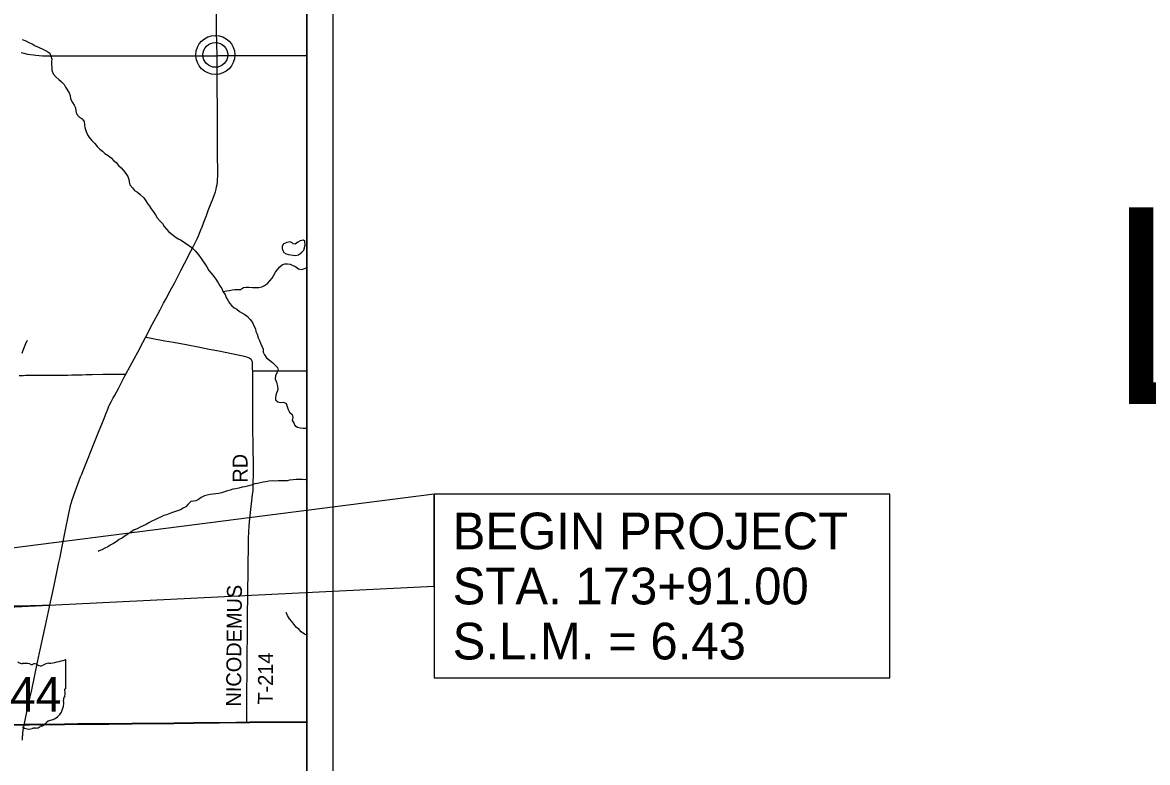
# Model space of a CAD drawing. Extents: x 0 to 34, y 0 to 22.
# Drawn here: x 7.83 to 12.121, y 17.09 to 19.912 of the extents above; entities that cross this region are included whole.
import ezdxf

# ---------------------------------------------------------------- set-up
doc = ezdxf.new("R2010")
doc.units = 0
for name, color, linetype in [('GM_X_Corporation', 7, 'Continuous'), ('GM_X_County_Road', 7, 'Continuous'), ('GM_X_Minor_Lake', 7, 'Continuous'), ('GM_X_Minor_River', 7, 'Continuous'), ('GM_X_State_Location', 7, 'Continuous'), ('GM_X_State_Route', 7, 'Continuous'), ('GM_X_State_Shield', 7, 'Continuous'), ('GM_X_Township_Road', 7, 'Continuous'), ('GM_X_Township_Road_Text', 7, 'Continuous'), ('GM_X_Unincorporated', 7, 'Continuous'), ('GM_X_Unincorporated_Location', 7, 'Continuous'), ('SH_Data', 7, 'Continuous'), ('SH_Text', 7, 'Continuous')]:
    doc.layers.add(name, color=color, linetype=linetype)

msp = doc.modelspace()

# ---------------------------------------------------------------- linework, layer by layer
at = {"layer": 'GM_X_Corporation'}
for points in [[(7.6782, 17.2342), (7.8362, 17.2347), (7.8566, 17.2348), (7.9908, 17.2361), (8.015, 17.2365), (8.0417, 17.237), (8.1363, 17.2369), (8.1597, 17.237), (8.2138, 17.2377), (8.2474, 17.2382), (8.3164, 17.2393), (8.4071, 17.2399), (8.4823, 17.2409), (8.5289, 17.2412), (8.5818, 17.2419), (8.6445, 17.2426), (8.6851, 17.2432), (8.6974, 17.2434), (8.762, 17.244), (8.8285, 17.2444), (8.8621, 17.2445), (8.914, 17.2449), (8.914, 20.6173), (5.0338, 20.6173)], [(5.0539, 13.8173), (8.914, 13.8173), (8.914, 17.2449), (8.8621, 17.2445), (8.8285, 17.2444), (8.762, 17.244), (8.6974, 17.2434), (8.6851, 17.2432), (8.6445, 17.2426), (8.5818, 17.2419), (8.5289, 17.2412), (8.4823, 17.2409), (8.4071, 17.2399), (8.3164, 17.2393), (8.2474, 17.2382), (8.2138, 17.2377), (8.1597, 17.237), (8.1363, 17.2369), (8.0417, 17.237), (8.015, 17.2365), (7.9908, 17.2361), (7.8566, 17.2348), (7.8362, 17.2347), (7.6782, 17.2342)]]:
    msp.add_lwpolyline(points, dxfattribs=at)
at = {"layer": 'GM_X_County_Road'}
for points in [[(7.8175, 18.5661), (7.8342, 18.5665), (7.8416, 18.5667), (7.8531, 18.5668), (7.8629, 18.5668), (7.8685, 18.5668), (7.8809, 18.5667), (7.902, 18.567), (7.9137, 18.5671), (7.9404, 18.567), (7.9683, 18.5672), (7.9881, 18.5675), (8.0037, 18.5678), (8.018, 18.5681), (8.0347, 18.5685), (8.0446, 18.5687), (8.0582, 18.569), (8.073, 18.5692), (8.0956, 18.5696), (8.1365, 18.5705), (8.1651, 18.5714), (8.1883, 18.5713), (8.2082, 18.5713), (8.2176, 18.5709), (8.2245, 18.5706)], [(7.0381, 17.229), (7.0647, 17.2291), (7.09, 17.2291), (7.1124, 17.2293), (7.1384, 17.2293), (7.1595, 17.2294), (7.305, 17.2305), (7.3566, 17.2307), (7.382, 17.2308), (7.5492, 17.2324), (7.62, 17.2331), (7.6784, 17.2336), (7.8364, 17.2342)], [(7.8364, 17.2342), (7.8568, 17.2342), (7.991, 17.2356), (8.0152, 17.2359), (8.0419, 17.2364), (8.1365, 17.2363), (8.1599, 17.2365), (8.214, 17.2371), (8.2476, 17.2376), (8.3166, 17.2387), (8.4073, 17.2394), (8.4825, 17.2403), (8.5291, 17.2407), (8.582, 17.2414), (8.6447, 17.242), (8.6853, 17.2427)], [(8.6853, 17.2427), (8.6976, 17.2429), (8.7622, 17.2435), (8.8287, 17.2439), (8.8623, 17.244), (8.914, 17.2444)]]:
    msp.add_lwpolyline(points, dxfattribs=at)
at = {"layer": 'GM_X_Minor_Lake'}
msp.add_line((8.8453, 19.0275), (8.8716, 19.0238), dxfattribs=at)
msp.add_lwpolyline([(8.8716, 19.0238), (8.8828, 19.0257), (8.8952, 19.0357), (8.9027, 19.0445), (8.9078, 19.0624), (8.9076, 19.0776), (8.9023, 19.0821), (8.8898, 19.0801), (8.88, 19.0747), (8.8699, 19.0673), (8.8627, 19.0684), (8.8588, 19.0721), (8.8505, 19.0755), (8.8384, 19.0734), (8.8244, 19.0664), (8.8203, 19.058), (8.8204, 19.0504), (8.8228, 19.0425), (8.8267, 19.0345), (8.8358, 19.0297), (8.8453, 19.0275)], dxfattribs=at)
at = {"layer": 'GM_X_Minor_River'}
for points in [[(7.8287, 19.8478), (7.8424, 19.8418), (7.8546, 19.8355), (7.8668, 19.8307), (7.8779, 19.8236), (7.8889, 19.8188), (7.9125, 19.8085), (7.9232, 19.8025), (7.9342, 19.7951), (7.9385, 19.7837), (7.9417, 19.7739), (7.941, 19.7629), (7.9408, 19.7534), (7.9417, 19.7397), (7.9425, 19.7302), (7.9476, 19.7166), (7.9572, 19.7049), (7.9691, 19.6948), (7.9786, 19.6858), (7.9893, 19.6753), (7.9948, 19.6655), (8.0079, 19.6444), (8.0114, 19.6334), (8.0134, 19.6205), (8.0208, 19.6069), (8.0273, 19.5971), (8.0327, 19.5866), (8.034, 19.5752), (8.036, 19.5642), (8.0464, 19.5522), (8.0582, 19.5443), (8.0659, 19.5346), (8.0664, 19.5216), (8.0681, 19.5114), (8.0728, 19.4963), (8.0786, 19.4842), (8.0859, 19.4725), (8.0947, 19.4627), (8.1055, 19.4503), (8.1151, 19.439), (8.1246, 19.4297), (8.135, 19.4211), (8.1445, 19.4128), (8.1563, 19.4046), (8.1678, 19.3956), (8.1774, 19.3858), (8.1869, 19.3776), (8.1962, 19.3667), (8.2061, 19.3573), (8.2157, 19.3476), (8.2245, 19.3359), (8.2322, 19.3246), (8.2361, 19.314), (8.237, 19.3045), (8.2401, 19.2935), (8.2494, 19.2819), (8.2578, 19.2713), (8.2689, 19.2646), (8.2796, 19.2568), (8.2926, 19.2429), (8.3003, 19.232), (8.3065, 19.2222), (8.3142, 19.2112), (8.3215, 19.2014), (8.3284, 19.1917), (8.3369, 19.1785), (8.3442, 19.1675), (8.3545, 19.1559), (8.3638, 19.1453), (8.3703, 19.134), (8.3799, 19.1239), (8.388, 19.1141), (8.3998, 19.1051), (8.4109, 19.0958), (8.4235, 19.0872), (8.433, 19.0835)], [(8.433, 19.0835), (8.4471, 19.0742), (8.4567, 19.0671), (8.4673, 19.06), (8.4788, 19.0514), (8.4891, 19.0416), (8.5033, 19.0243), (8.5118, 19.0126), (8.5191, 19.0013), (8.5257, 18.9915), (8.5334, 18.9799), (8.5407, 18.9666), (8.5499, 18.9557), (8.5599, 18.9437), (8.5676, 18.9335), (8.5765, 18.9192), (8.5823, 18.9075), (8.5903, 18.8973), (8.5946, 18.8864), (8.6027, 18.8743), (8.6074, 18.8634), (8.6139, 18.8532), (8.6194, 18.8422), (8.6282, 18.8321), (8.6377, 18.8238), (8.6473, 18.819), (8.6572, 18.8104), (8.6671, 18.8052), (8.6786, 18.7981), (8.6881, 18.791), (8.6988, 18.7801), (8.7073, 18.7685), (8.7131, 18.7556), (8.7185, 18.7443), (8.7198, 18.7333), (8.7248, 18.7231), (8.7288, 18.7098), (8.7342, 18.6997), (8.7385, 18.6891), (8.7431, 18.6781), (8.7482, 18.6664), (8.7487, 18.6554), (8.7526, 18.6444), (8.7603, 18.6335), (8.7725, 18.6238), (8.7832, 18.6152), (8.7932, 18.6062), (8.8028, 18.5964), (8.8048, 18.5858), (8.8003, 18.5762), (8.7955, 18.5644), (8.7934, 18.5534), (8.7985, 18.5401), (8.802, 18.5303), (8.804, 18.5167), (8.8022, 18.5072), (8.7974, 18.4957), (8.7949, 18.4839), (8.795, 18.4733), (8.8046, 18.4658), (8.8141, 18.4632), (8.8251, 18.4637), (8.8357, 18.4597), (8.84, 18.4476), (8.8428, 18.4362), (8.8482, 18.4264), (8.8581, 18.4178), (8.8613, 18.4053), (8.8584, 18.3946), (8.8653, 18.3848), (8.8692, 18.375), (8.8788, 18.3691), (8.8909, 18.3669), (8.9008, 18.3651), (8.9114, 18.3645), (8.914, 18.3646)], [(8.5946, 18.8864), (8.6098, 18.8888), (8.6196, 18.8897), (8.6298, 18.8921), (8.6396, 18.8941), (8.6506, 18.8939), (8.662, 18.894), (8.6736, 18.901), (8.6835, 18.9026), (8.6933, 18.9023), (8.7073, 18.9018), (8.7191, 18.9011), (8.7312, 18.9013), (8.7429, 18.9044), (8.7527, 18.9087), (8.7644, 18.9165), (8.773, 18.9264), (8.7823, 18.9376), (8.789, 18.949), (8.7953, 18.9605), (8.8039, 18.9712), (8.811, 18.9808), (8.8215, 18.9897), (8.8313, 18.9921), (8.8408, 18.9914), (8.851, 18.9904), (8.8613, 18.9856), (8.8708, 18.9815), (8.883, 18.9722), (8.8925, 18.9704), (8.9031, 18.9728), (8.914, 18.9782)], [(7.8284, 18.6507), (7.8332, 18.6629), (7.8384, 18.6748), (7.8428, 18.6885), (7.8479, 18.6996), (7.8487, 18.7)], [(8.914, 18.169), (8.9102, 18.1682), (8.8984, 18.1692), (8.887, 18.1698), (8.8742, 18.1693), (8.8621, 18.168), (8.8488, 18.1671), (8.839, 18.1647), (8.8261, 18.1641), (8.8049, 18.1639), (8.7936, 18.1634), (8.7818, 18.164), (8.7697, 18.1627), (8.7587, 18.1607), (8.7478, 18.1594), (8.7372, 18.157), (8.7262, 18.1546), (8.716, 18.1522), (8.7025, 18.1479), (8.6885, 18.1443), (8.6787, 18.1415), (8.6681, 18.1399), (8.6549, 18.1367), (8.6443, 18.1343), (8.6329, 18.1319), (8.6228, 18.1287), (8.6118, 18.1259), (8.6009, 18.122), (8.5895, 18.1185), (8.5793, 18.1164), (8.5676, 18.1152), (8.5578, 18.1135), (8.5461, 18.1115), (8.5347, 18.1098), (8.5238, 18.1071), (8.5121, 18.1009)], [(8.5121, 18.1009), (8.502, 18.0924), (8.4918, 18.0885), (8.4819, 18.0872), (8.4717, 18.0848), (8.4624, 18.0752), (8.453, 18.0648), (8.4429, 18.0594), (8.4323, 18.0532), (8.418, 18.0489), (8.4055, 18.0449), (8.3923, 18.0402), (8.3799, 18.0351), (8.3689, 18.0316), (8.3561, 18.0257), (8.3448, 18.0203), (8.335, 18.0152), (8.3237, 18.0109), (8.3124, 18.0036), (8.3023, 17.9974), (8.2925, 17.9942), (8.2793, 17.9876), (8.2672, 17.9818), (8.2563, 17.9775), (8.2439, 17.9686), (8.2319, 17.9609), (8.2221, 17.9547), (8.2112, 17.947), (8.1995, 17.9404), (8.1879, 17.9319), (8.1773, 17.9253), (8.1672, 17.9202), (8.1555, 17.9121), (8.1442, 17.9078), (8.1333, 17.9012), (8.1227, 17.8977), (8.1186, 17.8946)], [(8.914, 17.5751), (8.9057, 17.5795), (8.8924, 17.5889), (8.8847, 17.5986), (8.8748, 17.6054), (8.8644, 17.6178), (8.8575, 17.6276), (8.8486, 17.6385), (8.8409, 17.6502), (8.8359, 17.6619), (8.8363, 17.6611)]]:
    msp.add_lwpolyline(points, dxfattribs=at)
at = {"layer": 'GM_X_State_Route'}
for points in [[(8.572, 19.7856), (8.5704, 19.8786), (8.5698, 19.9413), (8.5693, 20.0004), (8.5683, 20.1116), (8.5679, 20.1484), (8.5676, 20.1747)], [(7.8245, 19.7977), (7.8359, 19.7947), (7.8498, 19.7915), (7.8607, 19.7897), (7.8718, 19.7882), (7.8817, 19.7873), (7.8934, 19.7864), (7.9065, 19.7856), (7.9436, 19.7846), (8.028, 19.7844), (8.1281, 19.7847), (8.2118, 19.7849)], [(8.2118, 19.7849), (8.2646, 19.7851), (8.3174, 19.7851), (8.3776, 19.7848), (8.5198, 19.7849), (8.572, 19.7856)], [(8.5133, 19.1277), (8.5137, 19.1286), (8.5223, 19.1512), (8.5314, 19.1757), (8.5389, 19.1954), (8.5486, 19.221), (8.5568, 19.2424), (8.562, 19.2558), (8.5658, 19.2669), (8.5688, 19.277), (8.5707, 19.2848), (8.5724, 19.2945), (8.5735, 19.3031), (8.5743, 19.313), (8.5747, 19.3266), (8.5743, 19.4244), (8.5742, 19.5077), (8.5734, 19.6027), (8.5732, 19.6449), (8.5729, 19.6912), (8.5729, 19.7215), (8.572, 19.7856)], [(8.572, 19.7856), (8.5777, 19.7857), (8.6355, 19.7859), (8.6858, 19.7859), (8.7386, 19.786), (8.7852, 19.786), (8.8417, 19.7861), (8.8809, 19.7861), (8.914, 19.7862)], [(8.4482, 18.9932), (8.4734, 19.042), (8.4824, 19.0597), (8.486, 19.0666), (8.4961, 19.0875), (8.5013, 19.0988), (8.5082, 19.1148), (8.5133, 19.1277)], [(7.8364, 17.2342), (7.8373, 17.2385), (7.8412, 17.258), (7.8537, 17.3143), (7.8652, 17.3672), (7.8876, 17.473), (7.8954, 17.5082), (7.9177, 17.6127), (7.9328, 17.6833), (7.9345, 17.6906), (7.9394, 17.7124), (7.9509, 17.7652), (7.9693, 17.8522), (7.9735, 17.8729), (7.9804, 17.907), (7.9946, 17.9777), (8.0057, 18.0337), (8.0151, 18.0757), (8.0155, 18.0772), (8.0196, 18.0915), (8.0218, 18.0986), (8.0256, 18.1092), (8.052, 18.1796), (8.0559, 18.1894), (8.0626, 18.2061), (8.1072, 18.3182), (8.1226, 18.3561), (8.1385, 18.3953), (8.1489, 18.4219), (8.1552, 18.4374), (8.16, 18.4488), (8.1623, 18.4539), (8.1682, 18.4655), (8.1721, 18.4726), (8.1764, 18.4802), (8.1805, 18.4879), (8.196, 18.5169), (8.2185, 18.5591), (8.2245, 18.5706), (8.2411, 18.602), (8.2557, 18.6294), (8.2695, 18.6551), (8.2886, 18.6914), (8.2991, 18.7111), (8.3038, 18.7199), (8.3188, 18.7485), (8.3328, 18.7748), (8.3459, 18.7995), (8.3547, 18.816), (8.3681, 18.8412), (8.3763, 18.8565), (8.3936, 18.8888), (8.4107, 18.9212), (8.434, 18.9658), (8.4482, 18.9932)], [(7.83, 17.1753), (7.8305, 17.1855), (7.8308, 17.1904), (7.831, 17.1939), (7.8316, 17.2012), (7.8328, 17.2118), (7.8342, 17.2212), (7.836, 17.2315), (7.8364, 17.2342)]]:
    msp.add_lwpolyline(points, dxfattribs=at)
at = {"layer": 'GM_X_State_Shield'}
for p, q in [((7.9958, 17.3741), (7.9958, 17.4787)), ((7.9957, 17.3741), (7.9958, 17.3741))]:
    msp.add_line(p, q, dxfattribs=at)
for centre, radius, start, end in [((7.8303, 17.497), 0.0296, 231.6195, 271.1119), ((7.8401, 17.3614), 0.1064, 80.4867, 94.9883), ((7.8643, 17.4718), 0.00855, 219.7921, 297.1024), ((7.8768, 17.4487), 0.0178, 54.4667, 119.1411), ((7.8997, 17.4804), 0.0214, 233.8562, 294.8282), ((7.9375, 17.4127), 0.0563, 97.3462, 120.7689), ((7.9018, 17.7466), 0.2796, 275.8445, 288.9065), ((7.9928, 17.4792), 0.00294, 351.8621, 97.738), ((8.0063, 17.3303), 0.0198, 136.8065, 186.9296), ((7.9951, 17.3664), 0.00454, 107.944, 210.337), ((7.9662, 17.3531), 0.0273, 340.033, 23.6496), ((7.9926, 17.3737), 0.00314, 289.6038, 7.7341), ((7.9175, 17.3169), 0.0699, 292.3089, 8.9858), ((7.947, 17.214), 0.0383, 94.4031, 142.5768), ((7.8556, 17.2577), 0.0401, 230.7004, 286.2918), ((7.8788, 17.1885), 0.0329, 85.6951, 111.2099), ((7.8817, 17.2427), 0.0214, 268.777, 315.5493), ((7.901, 17.2233), 0.00601, 65.7517, 132.6484), ((7.8985, 17.2508), 0.0226, 282.8732, 323.2771)]:
    msp.add_arc(centre, radius, start, end, dxfattribs=at)
at = {"layer": 'GM_X_Township_Road'}
for points in [[(8.7082, 18.5834), (8.708, 18.5895), (8.7078, 18.6007), (8.7078, 18.6038), (8.7076, 18.6139), (8.7069, 18.6171), (8.7058, 18.6207), (8.7032, 18.6252), (8.702, 18.6267), (8.6987, 18.6298), (8.6961, 18.6316), (8.6916, 18.6339), (8.6856, 18.6359), (8.677, 18.638), (8.6332, 18.6472), (8.579, 18.6582), (8.5417, 18.6653), (8.5064, 18.6725), (8.4539, 18.6825), (8.4062, 18.6912), (8.3726, 18.6974), (8.3268, 18.706), (8.3085, 18.7094), (8.2991, 18.7111)], [(8.6853, 17.2427), (8.6853, 17.2495), (8.6853, 17.2891), (8.6857, 17.312), (8.6858, 17.3282), (8.6859, 17.3431), (8.6859, 17.3686), (8.6865, 17.4245), (8.6865, 17.4426), (8.6868, 17.4612), (8.6872, 17.4935), (8.6874, 17.5159), (8.6882, 17.5594), (8.6886, 17.596), (8.6888, 17.624), (8.6889, 17.6451), (8.6886, 17.6737), (8.689, 17.7048), (8.6898, 17.7458), (8.6909, 17.8129), (8.6913, 17.8614), (8.6918, 17.8956), (8.6924, 17.9229), (8.6925, 17.9428), (8.6933, 17.9707), (8.6943, 17.9912), (8.6957, 18.0079), (8.6994, 18.0431), (8.7051, 18.0881), (8.708, 18.1116), (8.7094, 18.1258), (8.7102, 18.1414), (8.7105, 18.1582), (8.7106, 18.1874), (8.7106, 18.2079), (8.7106, 18.239), (8.71, 18.2763), (8.7094, 18.3123), (8.7089, 18.3521), (8.709, 18.3807), (8.7088, 18.4167), (8.709, 18.4577), (8.709, 18.4913), (8.7091, 18.505), (8.7086, 18.5336), (8.7086, 18.559), (8.7085, 18.5777), (8.7082, 18.5834)], [(8.7082, 18.5834), (8.7133, 18.5835), (8.7237, 18.5836), (8.7634, 18.5838), (8.7965, 18.5836), (8.8366, 18.5836), (8.8708, 18.5833), (8.9074, 18.5835), (8.914, 18.5835)], [(7.5895, 17.6821), (7.7873, 17.687), (7.814, 17.6878), (7.9048, 17.6903), (7.9345, 17.6906)]]:
    msp.add_lwpolyline(points, dxfattribs=at)
at = {"layer": 'GM_X_Unincorporated'}
for radius in [0.0744, 0.0472]:
    msp.add_circle((8.5657, 19.7886), radius, dxfattribs=at)
at = {"layer": 'GM_X_Unincorporated_Location'}
msp.add_line((8.5657, 19.7886), (8.5657, 19.7886), dxfattribs=at)
at = {"layer": 'SH_Data'}
for p, q in [((9.014, 20.7173), (9.014, 13.7173)), ((8.914, 20.6173), (8.914, 13.8173))]:
    msp.add_line(p, q, dxfattribs=at)
at = {"layer": 'SH_Text'}
for points in [[(9.4006, 18.113), (4.9378, 17.5422), (9.4006, 17.763)], [(9.4006, 17.413), (11.1382, 17.413), (11.1382, 18.113), (9.4006, 18.113)]]:
    msp.add_lwpolyline(points, close=True, dxfattribs=at)

# ---------------------------------------------------------------- texts
at = {"layer": 'GM_X_State_Location'}
for s, p in [('s', (7.861, 17.357)), ('r', (7.8609, 17.357))]:
    msp.add_text(s, height=0.000189, dxfattribs=at).set_placement(p)
at = {"layer": 'GM_X_State_Shield'}
msp.add_text('44', height=0.13184, dxfattribs=at).set_placement((7.7827, 17.2843))
at = {"layer": 'GM_X_Township_Road_Text'}
for s, rotation, p in [('RD', 90, (8.6884, 18.1571)), ('NICODEMUS', 89.5401, (8.6634, 17.3031)), ('T-214', 89.4555, (8.7844, 17.3106))]:
    msp.add_text(s, height=0.05682, rotation=rotation, dxfattribs=at).set_placement(p)
at = {"layer": 'SH_Data'}
msp.add_text('LEGEND SHEET', height=0.75, dxfattribs=at).set_placement((11.9677, 18.4573))
at = {"layer": 'SH_Text'}
for s, p in [('BEGIN PROJECT', (9.4706, 17.903)), ('STA. 173+91.00', (9.4706, 17.693)), ('S.L.M. = 6.43', (9.4706, 17.483))]:
    msp.add_text(s, height=0.14, dxfattribs=at).set_placement(p)

doc.saveas('drawing.dxf')
